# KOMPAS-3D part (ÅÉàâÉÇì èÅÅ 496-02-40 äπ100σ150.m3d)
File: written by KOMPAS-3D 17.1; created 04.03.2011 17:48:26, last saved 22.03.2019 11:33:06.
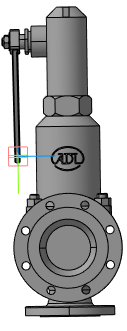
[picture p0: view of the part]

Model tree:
1. Плоскость XY
2. Плоскость ZX
3. Плоскость ZY
4. Ось X
5. Ось Y
6. Ось Z
7. Начало координат
8. Операция без истории:2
